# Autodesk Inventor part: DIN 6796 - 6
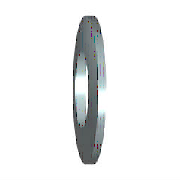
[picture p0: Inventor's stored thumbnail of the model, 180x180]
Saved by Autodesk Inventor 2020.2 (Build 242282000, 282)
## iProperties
Manager: www.cadconsulting.pl
Company: Fabian Stasiak CAD Consulting
Created: 2010-02
Part Number: DIN 6796 - 6
Material: Stal, miękka
Description: Podkładka sprężysta stożkowa
Document SubType Name: Modeling
Standard: DIN 6796
Designer: F.Stasiak
Standard Revision: 1987
Standards Organization: DIN
Language: pl-PL
Size Designation: 6
Categories: <MemberInstance><Categories><Category DisplayName="Mocowania" InternalName="e4da775c-781d-43d5-af7c-5136215cf5a6" Mnemonic="FSTN"><Category DisplayName="Podkład
Density: 1 g/cm^3
Appearance: Stal
IsCustomPart: 0
Author: F.Stasiak
Subject: Zbiór ćwiczeń. Autodesk Inventor 2020. Kurs podstawowy
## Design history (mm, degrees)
sketch "Sketch"
  geometry: C1 r 7 at (0, 0); C2 r 3.2 at (0, 0); 1 further point
  constraints: 2 centre point, 2 coincident
  dimensions: "d0" = 6.4 diameter of C2 (= SD1); "d1" = 14 diameter of C1 (= SD2)
extrude "Body" new body sketch "Sketch" distance "d2" = 1.5 (= SD); taper "d3" = 0 deg
workaxis "Work Axis1"
workplane "Work Plane1"
body "Solid1"
other parameters: "SD1" = 6.4 [user parameter; used in 1 equation term], "SD2" = 14 [user parameter; used in 1 equation term], "SD" = 1.5 [user parameter; used in 1 equation term], "d4" = 0, "d5" = 0, "d6" = 0, "d7" = 0, "NND" = 6 [user parameter]
